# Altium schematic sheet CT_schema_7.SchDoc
size 274 x 160 mm
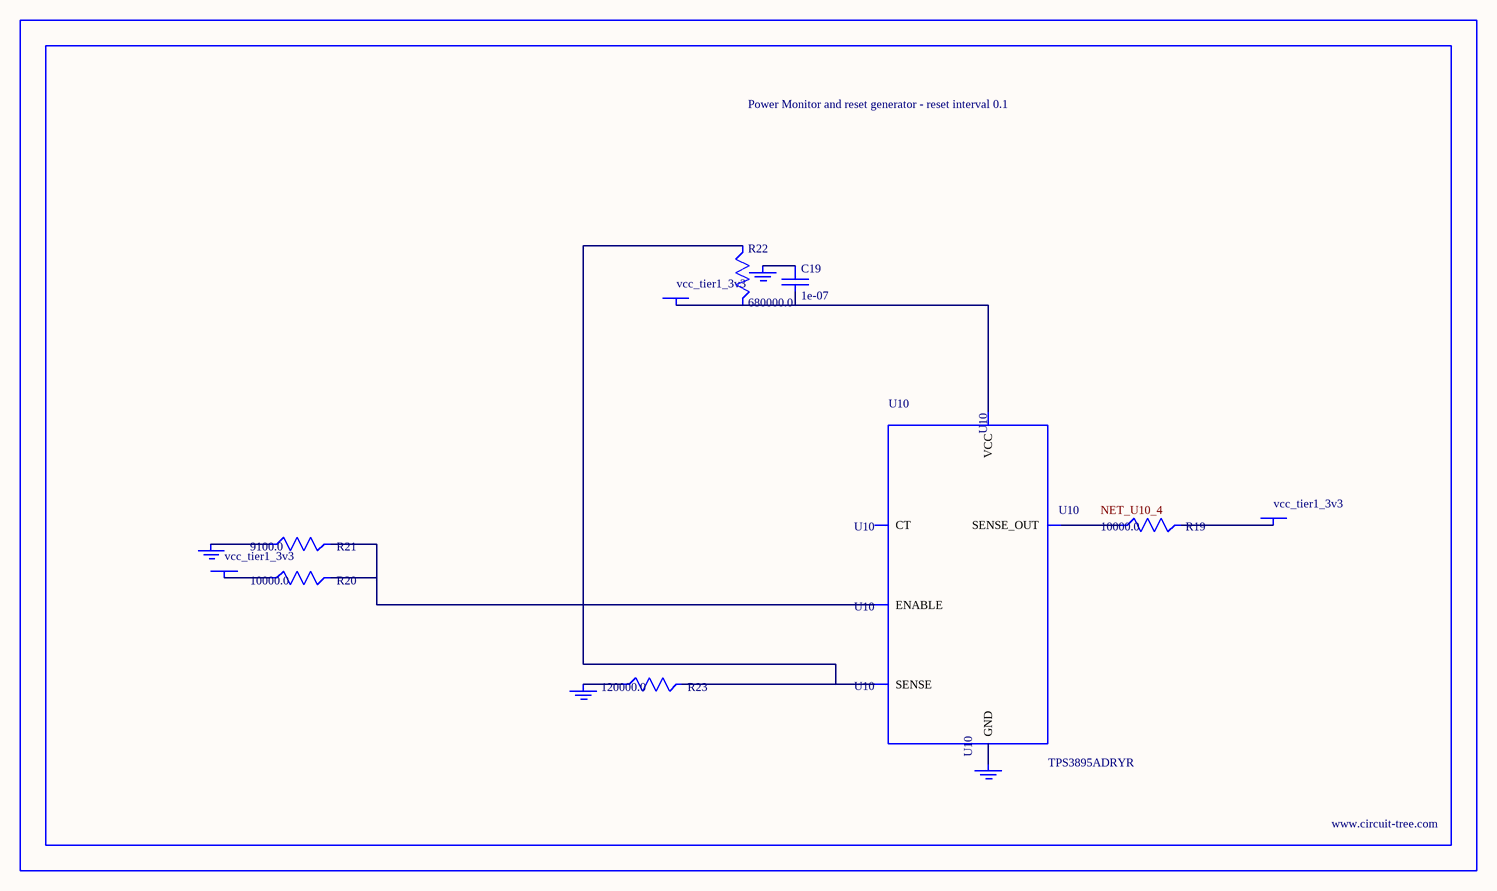
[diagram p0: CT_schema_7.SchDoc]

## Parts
BORDER6  (no value)
C19  1e-07  [C0402]
GND_INSTANCE_6_0  (no value)
GND_INSTANCE_6_1  (no value)
GND_INSTANCE_6_2  (no value)
GND_INSTANCE_6_3  (no value)
POWER_INSTANCE_6_0  vcc_tier1_3v3
POWER_INSTANCE_6_1  vcc_tier1_3v3
POWER_INSTANCE_6_2  vcc_tier1_3v3
R19  10000.0  [R0603]
R20  10000.0  [R0603]
R21  9100.0  [R0603]
R22  680000.0  [R0603]
R23  120000.0  [R0603]
U10  TPS3895ADRYR  [SON-6]

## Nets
NetC19_1: C19.1 GND_INSTANCE_6_2.0(GND)
NetC19_2: C19.2 POWER_INSTANCE_6_2.0(PWR) R22.2 U10.6(VCC)
NetGND_INSTANCE_6_0_0: GND_INSTANCE_6_0.0(GND) R21.1
NetGND_INSTANCE_6_1_0: GND_INSTANCE_6_1.0(GND) R23.1
NetGND_INSTANCE_6_3_0: GND_INSTANCE_6_3.0(GND) U10.2(GND)
NetPOWER_INSTANCE_6_0_0: POWER_INSTANCE_6_0.0(PWR) R20.1
NetPOWER_INSTANCE_6_1_0: POWER_INSTANCE_6_1.0(PWR) R19.2
NetR19_1: R19.1 U10.4(SENSE_OUT)
NetR20_2: R20.2 R21.2 U10.1(ENABLE)
NetR22_1: R22.1 R23.2 U10.3(SENSE)

Not connected (* = marked no-connect by the designer): U10 5(CT)

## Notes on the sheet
- Labels drawn without touching a wire or pin: NET_U10_4

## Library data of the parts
BORDER6 = BORDER_PAGE6
C19 = C0402C104K3RACTU
GND_INSTANCE_6_0-GND_INSTANCE_6_3 = GND
POWER_INSTANCE_6_0-POWER_INSTANCE_6_2 = PWR
R19 R20 = RC0603JR-0710KL
R21 = RC0603JR-079K1L
R22 = RC0603JR-07680KL
R23 = RC0603JR-07120KL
